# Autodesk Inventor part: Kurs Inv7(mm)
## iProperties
Shininess: 64.0
Length Units: 11269
Angle Units: 11279
Time Units: 11290
Mass Units: 11283
Length Display Precision: 3
Angle Display Precision: 2
Compacted: True
Created: 2003-08
Part Number: Kurs Inv7(mm)
Material: Steel, Mild
Document SubType Name: Modeling
Designer: Administratör
Manufacturer: Standard
Standards Organization: Custom
Density: 0.0
Volumn: 0.0
Area: 0.0
PropertySet Name: Model Information
Control State: 0
Master: False
Checked Out: False
Author: Administratör
